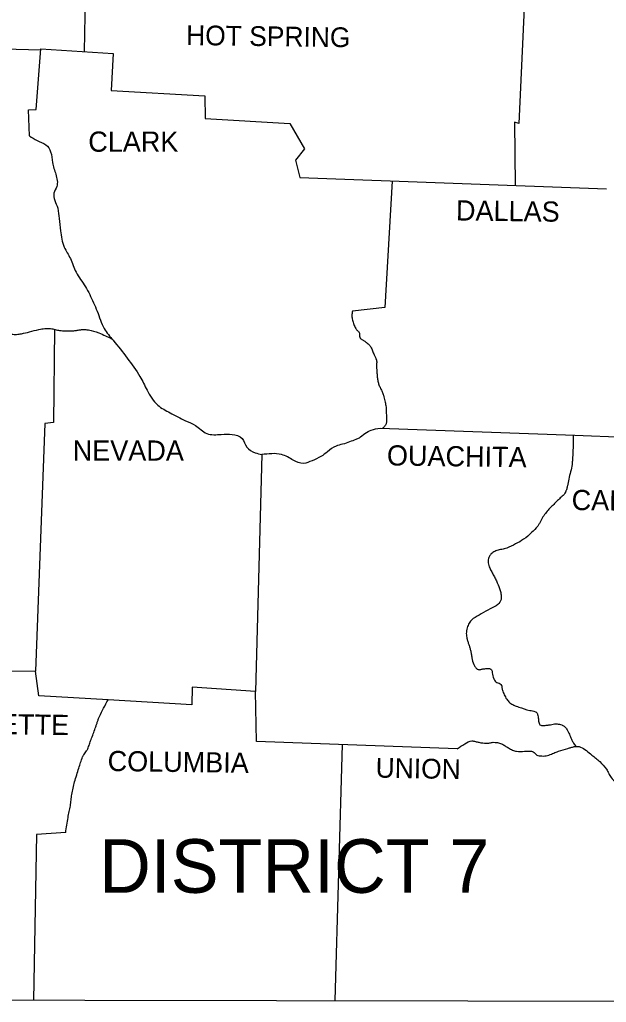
# Model space of a CAD drawing. Extents: x 1334737.7 to 1334827.2, y 402732.3 to 402753.5.
# Drawn here: x 1334763.502 to 1334764.914, y 402745.105 to 402747.469 of the extents above; entities that cross this region are included whole.
import ezdxf

# ---------------------------------------------------------------- set-up
doc = ezdxf.new("R2010")
doc.units = 0
doc.layers.add('Default', color=7, linetype='Continuous')

msp = doc.modelspace()

# ---------------------------------------------------------------- linework, layer by layer
at = {"layer": 'Default'}
msp.add_line((1334763.6708, 402748.1026), (1334763.6576, 402747.3922), dxfattribs=at)
for points in [[(1334764.7171, 402747.5155), (1334764.7035, 402747.2192), (1334764.6933, 402747.2225), (1334764.6944, 402747.07)], [(1334762.8982, 402747.4138), (1334763.5529, 402747.3966)], [(1334763.526, 402747.1897), (1334763.5237, 402747.252), (1334763.5418, 402747.2531), (1334763.5531, 402747.399), (1334763.7273, 402747.3877), (1334763.7228, 402747.2983), (1334763.9479, 402747.2859), (1334763.949, 402747.2316), (1334764.1526, 402747.2192), (1334764.1877, 402747.1581), (1334764.1662, 402747.1309), (1334764.1764, 402747.0891), (1334764.9139, 402747.0619)], [(1334764.3989, 402747.0809), (1334764.3811, 402746.7769), (1334764.3031, 402746.7678)], [(1334763.5859, 402746.7243), (1334763.5837, 402746.4998), (1334763.5633, 402746.4975), (1334763.5407, 402745.9014)], [(1334764.3698, 402746.4862), (1334764.8381, 402746.4692), (1334765.2014, 402746.455)], [(1334764.0848, 402746.4228), (1334764.0701, 402745.8528), (1334763.9174, 402745.8629), (1334763.9162, 402745.8211), (1334763.7149, 402745.8329)], [(1334762.7353, 402746.027), (1334762.7376, 402745.1119), (1334766.8832, 402745.1051)], [(1334763.5407, 402745.9014), (1334763.1979, 402745.898)], [(1334763.7149, 402745.8329), (1334763.5486, 402745.8426), (1334763.5407, 402745.9014)], [(1334764.5553, 402745.7148), (1334764.0723, 402745.7329), (1334764.0701, 402745.8528)], [(1334764.2783, 402745.7251), (1334764.2603, 402745.1094)], [(1334763.6131, 402745.5134), (1334763.5429, 402745.5089), (1334763.5353, 402745.1106)]]:
    msp.add_lwpolyline(points, dxfattribs=at)
for points in [[(1334763.526, 402747.1897), (1334763.5441, 402747.1784), (1334763.5656, 402747.1683), (1334763.5769, 402747.1513), (1334763.5814, 402747.1253), (1334763.5893, 402747.097), (1334763.5916, 402747.0676), (1334763.5848, 402747.0518), (1334763.5938, 402747.0156), (1334763.5972, 402746.9907), (1334763.6006, 402746.9613), (1334763.6097, 402746.9217), (1334763.6244, 402746.8945), (1334763.638, 402746.8617), (1334763.6606, 402746.8267), (1334763.6798, 402746.7882), (1334763.6889, 402746.7678), (1334763.7058, 402746.726), (1334763.7273, 402746.6977), (1334763.7613, 402746.6547), (1334763.7918, 402746.6106), (1334763.8088, 402746.5778), (1334763.8348, 402746.5416), (1334763.8642, 402746.5235), (1334763.9015, 402746.5043), (1334763.9253, 402746.493), (1334763.9524, 402746.4737), (1334763.9875, 402746.4715), (1334764.0135, 402746.4715), (1334764.0373, 402746.4613), (1334764.0486, 402746.4409), (1334764.0689, 402746.4274), (1334764.0848, 402746.4228)], [(1334763.0629, 402746.8153), (1334763.1108, 402746.8108), (1334763.1504, 402746.8063), (1334763.1658, 402746.8051), (1334763.1734, 402746.8043), (1334763.1772, 402746.8037), (1334763.181, 402746.8029), (1334763.1891, 402746.8005), (1334763.197, 402746.7977), (1334763.2126, 402746.7916), (1334763.2409, 402746.7814), (1334763.2455, 402746.7795), (1334763.2499, 402746.7774), (1334763.2544, 402746.7753), (1334763.259, 402746.7735), (1334763.2665, 402746.7727), (1334763.2742, 402746.774), (1334763.2819, 402746.7756), (1334763.2896, 402746.7758), (1334763.3026, 402746.7733), (1334763.3156, 402746.7701), (1334763.3307, 402746.7661), (1334763.338, 402746.7635), (1334763.3415, 402746.7619), (1334763.345, 402746.7599), (1334763.3563, 402746.7509), (1334763.3665, 402746.7407), (1334763.3697, 402746.7371), (1334763.3727, 402746.7332), (1334763.3801, 402746.726), (1334763.3864, 402746.7226), (1334763.3929, 402746.7209), (1334763.4061, 402746.7203), (1334763.4114, 402746.721), (1334763.4168, 402746.7221), (1334763.4222, 402746.7232), (1334763.4276, 402746.7237), (1334763.4536, 402746.7215), (1334763.461, 402746.7195), (1334763.4683, 402746.7167), (1334763.4756, 402746.7141), (1334763.483, 402746.7124), (1334763.4889, 402746.712), (1334763.4949, 402746.712), (1334763.5067, 402746.7135), (1334763.526, 402746.7181), (1334763.5486, 402746.7237), (1334763.5627, 402746.7259), (1334763.5698, 402746.7262), (1334763.5769, 402746.726), (1334763.5823, 402746.7252), (1334763.5876, 402746.7238), (1334763.593, 402746.7224), (1334763.5984, 402746.7215), (1334763.6125, 402746.7206), (1334763.6266, 402746.7203), (1334763.6349, 402746.721), (1334763.6431, 402746.7223), (1334763.6513, 402746.7235), (1334763.6554, 402746.7238), (1334763.6595, 402746.7237), (1334763.6678, 402746.7227), (1334763.6925, 402746.7155), (1334763.7085, 402746.7087), (1334763.7242, 402746.7016)], [(1334764.3031, 402746.7678), (1334764.3018, 402746.7571), (1334764.3022, 402746.7517), (1334764.3031, 402746.7463), (1334764.3044, 402746.7411), (1334764.3062, 402746.7359), (1334764.3084, 402746.7309), (1334764.311, 402746.726), (1334764.3128, 402746.7235), (1334764.3149, 402746.7214), (1334764.3171, 402746.7192), (1334764.3189, 402746.7169), (1334764.32, 402746.7134), (1334764.3202, 402746.7094), (1334764.3206, 402746.7054), (1334764.3212, 402746.7037), (1334764.3223, 402746.7022), (1334764.3247, 402746.7003), (1334764.3273, 402746.6987), (1334764.33, 402746.6972), (1334764.3325, 402746.6954), (1334764.3345, 402746.6939), (1334764.3365, 402746.6924), (1334764.3406, 402746.6893), (1334764.3443, 402746.6859), (1334764.3459, 402746.684), (1334764.3472, 402746.6819), (1334764.3494, 402746.6771), (1334764.3513, 402746.6723), (1334764.3532, 402746.6674), (1334764.3551, 402746.6626), (1334764.3581, 402746.6565), (1334764.3596, 402746.6535), (1334764.3602, 402746.6519), (1334764.3608, 402746.6502), (1334764.3613, 402746.6463), (1334764.3612, 402746.6423), (1334764.3608, 402746.6383), (1334764.3608, 402746.6344), (1334764.3613, 402746.6264), (1334764.3619, 402746.6185), (1334764.3628, 402746.6089), (1334764.3634, 402746.6041), (1334764.3642, 402746.5993), (1334764.3668, 402746.5906), (1334764.3706, 402746.5822), (1334764.3746, 402746.5739), (1334764.3777, 402746.5654), (1334764.3811, 402746.5518), (1334764.3834, 402746.5405), (1334764.3845, 402746.5213), (1334764.3847, 402746.5156), (1334764.3848, 402746.5099), (1334764.3848, 402746.5043), (1334764.3847, 402746.5015), (1334764.3845, 402746.4986), (1334764.3835, 402746.4954), (1334764.3813, 402746.4919), (1334764.3752, 402746.486)], [(1334764.3189, 402746.4624), (1334764.3483, 402746.4817), (1334764.3698, 402746.4862)], [(1334764.3189, 402746.4624), (1334764.3108, 402746.4591), (1334764.2963, 402746.4534), (1334764.2793, 402746.4477), (1334764.2635, 402746.4432), (1334764.2431, 402746.4296), (1334764.2273, 402746.4183), (1334764.2058, 402746.4081), (1334764.1854, 402746.4014), (1334764.1606, 402746.4093), (1334764.147, 402746.4172), (1334764.1323, 402746.4228), (1334764.0848, 402746.4228)], [(1334764.8343, 402746.4694), (1334764.8336, 402746.4342), (1334764.8328, 402746.4166), (1334764.8322, 402746.4079), (1334764.8313, 402746.3991), (1334764.8279, 402746.3815), (1334764.8234, 402746.364), (1334764.8204, 402746.348), (1334764.8185, 402746.3401), (1334764.8172, 402746.3362), (1334764.8164, 402746.3343), (1334764.8155, 402746.3324), (1334764.8121, 402746.3271), (1334764.8078, 402746.3226), (1334764.7985, 402746.3143), (1334764.7894, 402746.3052), (1334764.7804, 402746.2962), (1334764.7635, 402746.2758), (1334764.7595, 402746.2697), (1334764.7561, 402746.2634), (1334764.7527, 402746.257), (1334764.7487, 402746.2509), (1334764.734, 402746.2351), (1334764.7148, 402746.2192), (1334764.6956, 402746.2079), (1334764.6741, 402746.1978), (1334764.6683, 402746.1959), (1334764.6623, 402746.1948), (1334764.6563, 402746.1937), (1334764.6503, 402746.1921), (1334764.6409, 402746.1873), (1334764.6369, 402746.1839), (1334764.6351, 402746.1819), (1334764.6334, 402746.1797), (1334764.6304, 402746.1731), (1334764.6294, 402746.1661), (1334764.6322, 402746.1525), (1334764.6368, 402746.1429), (1334764.6419, 402746.1334), (1334764.6469, 402746.1238), (1334764.6515, 402746.114), (1334764.6583, 402746.096), (1334764.6597, 402746.0907), (1334764.6607, 402746.0853), (1334764.661, 402746.0798), (1334764.6605, 402746.0745), (1334764.6526, 402746.062), (1334764.6345, 402746.0518), (1334764.613, 402746.0394), (1334764.5938, 402746.0281), (1334764.5892, 402746.0244), (1334764.5855, 402746.0198), (1334764.5826, 402746.0145), (1334764.5802, 402746.0089), (1334764.5772, 402745.9958), (1334764.5779, 402745.9828), (1334764.58, 402745.9752), (1334764.5824, 402745.9676), (1334764.5849, 402745.96), (1334764.587, 402745.9523), (1334764.5887, 402745.9433), (1334764.5904, 402745.9342), (1334764.5947, 402745.9182), (1334764.5987, 402745.9112), (1334764.6015, 402745.9083), (1334764.6032, 402745.907), (1334764.6051, 402745.9059), (1334764.6079, 402745.9053), (1334764.6107, 402745.9057), (1334764.6136, 402745.9066), (1334764.6164, 402745.9071), (1334764.6189, 402745.9072), (1334764.6215, 402745.9076), (1334764.6266, 402745.9083), (1334764.6317, 402745.9081), (1334764.6342, 402745.9074), (1334764.6355, 402745.9067), (1334764.6368, 402745.9059), (1334764.6385, 402745.9033), (1334764.639, 402745.9003), (1334764.6402, 402745.8946), (1334764.6447, 402745.8799), (1334764.648, 402745.8761), (1334764.6531, 402745.8736), (1334764.6582, 402745.8712), (1334764.6617, 402745.8675), (1334764.6624, 402745.8647), (1334764.6628, 402745.8618), (1334764.6632, 402745.8589), (1334764.6639, 402745.8562), (1334764.6682, 402745.8452), (1334764.6741, 402745.8347), (1334764.6777, 402745.8301), (1334764.6817, 402745.826), (1334764.6911, 402745.82), (1334764.7035, 402745.8154), (1334764.7295, 402745.8075), (1334764.7431, 402745.8041), (1334764.745, 402745.8032), (1334764.7486, 402745.7977), (1334764.7503, 402745.7868), (1334764.7521, 402745.7763), (1334764.7542, 402745.7728), (1334764.7578, 402745.7713), (1334764.7668, 402745.7714), (1334764.7759, 402745.7725), (1334764.7895, 402745.7747), (1334764.8009, 402745.7742), (1334764.8066, 402745.7723), (1334764.8093, 402745.7708), (1334764.8121, 402745.7691), (1334764.8182, 402745.7627), (1334764.8223, 402745.7555), (1334764.825, 402745.7499), (1334764.8273, 402745.7442), (1334764.8297, 402745.7385), (1334764.8325, 402745.7329), (1334764.8384, 402745.7242), (1334764.8416, 402745.7209)], [(1334763.6131, 402745.5134), (1334763.6187, 402745.5496), (1334763.62, 402745.5567), (1334763.6215, 402745.5638), (1334763.623, 402745.5708), (1334763.6244, 402745.5779), (1334763.6254, 402745.5847), (1334763.6261, 402745.5915), (1334763.6268, 402745.5983), (1334763.6278, 402745.605), (1334763.6346, 402745.6356), (1334763.6447, 402745.6684), (1334763.6538, 402745.6955), (1334763.655, 402745.6981), (1334763.6564, 402745.7006), (1334763.66, 402745.7052), (1334763.6635, 402745.7098), (1334763.665, 402745.7122), (1334763.6662, 402745.7148), (1334763.6683, 402745.7204), (1334763.6702, 402745.7261), (1334763.6721, 402745.7317), (1334763.6742, 402745.7374), (1334763.6843, 402745.7645), (1334763.6868, 402745.7717), (1334763.689, 402745.7788), (1334763.6915, 402745.7859), (1334763.6945, 402745.7928), (1334763.7149, 402745.8329)], [(1334764.5553, 402745.7148), (1334764.5734, 402745.7272), (1334764.5904, 402745.734), (1334764.5988, 402745.7325), (1334764.6031, 402745.7315), (1334764.6074, 402745.7306), (1334764.6255, 402745.7283), (1334764.6294, 402745.7285), (1334764.6334, 402745.7293), (1334764.6373, 402745.7302), (1334764.6413, 402745.7306), (1334764.6617, 402745.7272), (1334764.6662, 402745.7249), (1334764.6703, 402745.7222), (1334764.6744, 402745.7195), (1334764.6786, 402745.717), (1334764.688, 402745.7119), (1334764.6978, 402745.7091), (1334764.7171, 402745.7091), (1334764.734, 402745.7091), (1334764.7381, 402745.7077), (1334764.7415, 402745.7044), (1334764.7449, 402745.701), (1334764.7487, 402745.6989), (1334764.7554, 402745.698), (1334764.7624, 402745.6977), (1334764.7693, 402745.6984), (1334764.7759, 402745.7001), (1334764.7816, 402745.7022), (1334764.7872, 402745.7046), (1334764.7928, 402745.707), (1334764.7985, 402745.7091), (1334764.8211, 402745.7159), (1334764.8288, 402745.7182), (1334764.8366, 402745.7202), (1334764.8444, 402745.7209), (1334764.8481, 402745.7205), (1334764.8517, 402745.7193), (1334764.8658, 402745.7106), (1334764.8788, 402745.7001), (1334764.8886, 402745.6923), (1334764.8981, 402745.6842), (1334764.9139, 402745.6661), (1334764.917, 402745.6612), (1334764.9196, 402745.656), (1334764.9221, 402745.6508), (1334764.9252, 402745.6458), (1334764.9377, 402745.6345), (1334764.9426, 402745.6319), (1334764.9476, 402745.6298), (1334764.958, 402745.6265), (1334764.9738, 402745.6231), (1334764.9931, 402745.6175), (1334764.9985, 402745.616), (1334765.0011, 402745.6148), (1334765.0033, 402745.613), (1334765.0065, 402745.6079), (1334765.0086, 402745.6024), (1334765.0103, 402745.5969), (1334765.0123, 402745.5915), (1334765.0139, 402745.5877), (1334765.0152, 402745.584), (1334765.0178, 402745.5766), (1334765.0213, 402745.5693), (1334765.0238, 402745.5657), (1334765.0253, 402745.5639), (1334765.027, 402745.5621), (1334765.0338, 402745.5564), (1334765.041, 402745.5527), (1334765.0482, 402745.5511), (1334765.0553, 402745.5519), (1334765.064, 402745.5549), (1334765.0728, 402745.5586), (1334765.0815, 402745.5623), (1334765.0904, 402745.5655), (1334765.1186, 402745.5734), (1334765.139, 402745.5802), (1334765.1514, 402745.5847), (1334765.1542, 402745.5852), (1334765.1571, 402745.5853), (1334765.16, 402745.5853), (1334765.1628, 402745.5858), (1334765.1629, 402745.586), (1334765.1626, 402745.5863), (1334765.1611, 402745.5869), (1334765.1596, 402745.5875), (1334765.1592, 402745.5878), (1334765.1594, 402745.5881), (1334765.1626, 402745.5896), (1334765.1661, 402745.5909), (1334765.1729, 402745.5915), (1334765.1762, 402745.5902), (1334765.1796, 402745.5881), (1334765.1854, 402745.5824), (1334765.1875, 402745.5793), (1334765.1894, 402745.5761), (1334765.1912, 402745.573), (1334765.1933, 402745.57), (1334765.2069, 402745.5519), (1334765.2128, 402745.5439), (1334765.2159, 402745.54), (1334765.2193, 402745.536), (1334765.2221, 402745.5337), (1334765.2253, 402745.5321), (1334765.2286, 402745.531), (1334765.2318, 402745.5304), (1334765.2348, 402745.5314), (1334765.2379, 402745.5341), (1334765.241, 402745.5366), (1334765.2442, 402745.5372), (1334765.2612, 402745.5315), (1334765.2759, 402745.5259), (1334765.2928, 402745.5213), (1334765.2965, 402745.5209), (1334765.3002, 402745.5207), (1334765.3039, 402745.5206), (1334765.3075, 402745.5202), (1334765.3268, 402745.5157), (1334765.3415, 402745.5078), (1334765.355, 402745.4999), (1334765.3686, 402745.4851), (1334765.3822, 402745.4625), (1334765.3837, 402745.4582), (1334765.3845, 402745.4536), (1334765.3853, 402745.4489), (1334765.3867, 402745.4444), (1334765.3934, 402745.4343), (1334765.3978, 402745.4301), (1334765.4026, 402745.4263), (1334765.4061, 402745.4256), (1334765.4103, 402745.4267), (1334765.4143, 402745.4276), (1334765.4173, 402745.4263), (1334765.4228, 402745.4191), (1334765.4282, 402745.4117), (1334765.4388, 402745.3969), (1334765.4467, 402745.3856), (1334765.454, 402745.3747), (1334765.4583, 402745.3697), (1334765.4608, 402745.3674), (1334765.4636, 402745.3652), (1334765.4666, 402745.3643), (1334765.4698, 402745.3646), (1334765.473, 402745.3652), (1334765.4761, 402745.3652), (1334765.5002, 402745.3606)]]:
    msp.add_spline(points, degree=3, dxfattribs=at)

# ---------------------------------------------------------------- texts
for s, height, rotation, p in [('HOT SPRING', 0.04751, 359.2216, (1334763.9026, 402747.4081)), ('DALLAS', 0.04863, 359.2462, (1334764.5519, 402746.9861)), ('OUACHITA', 0.04865, 359.2043, (1334764.3857, 402746.3968)), ('CALHOUN', 0.04865, 359.3634, (1334764.8302, 402746.2894)), ('LAFAYETTE', 0.04863, 359.1839, (1334763.2488, 402745.7532)), ('COLUMBIA', 0.04863, 359.2125, (1334763.7137, 402745.6616)), ('UNION', 0.04751, 358.9584, (1334764.3585, 402745.6458))]:
    msp.add_text(s, height=height, rotation=rotation, dxfattribs=at).set_placement(p)
for s, height, p in [('CLARK', 0.04864, (1334763.6674, 402747.1513)), ('NEVADA', 0.04864, (1334763.63, 402746.4081)), ('DISTRICT 7', 0.12895, (1334763.6934, 402745.3686))]:
    msp.add_text(s, height=height, dxfattribs=at).set_placement(p)

doc.saveas('drawing.dxf')
